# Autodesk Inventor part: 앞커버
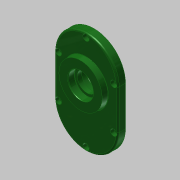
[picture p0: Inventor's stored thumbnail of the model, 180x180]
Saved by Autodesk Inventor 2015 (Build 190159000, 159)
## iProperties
Created: 2016-12
Part Number: 앞커버
Material: 일반
Document SubType Name: Modeling
Designer: mduedu
Density: 1 g/cm^3
Appearance: 매끄러움 - 짙은 산림 녹색
Mass: 97.664 g
Surface Area: 264.413 cm^2
Volume: 97.664 cm^3
Author: mduedu
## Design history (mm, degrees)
sketch "스케치1"
  geometry: L1 (40, -25)-(40, 25); L2 (-40, 25)-(-40, -25); L3 (-40, -25)-(40, 25); L4 (40, -25)-(-40, 25); A1 r 40 centre (0, 25) between (40, 25) and (-40, 25); A2 r 40 centre (0, -25) between (-40, -25) and (40, -25); 1 further point
  constraints: 8 end point, 4 point on circle, 4 tangent, 2 centre point, 2 midpoint, 1 parallel, 1 vertical
  dimensions: "d0" = 130 dimension on A2 A1; "d2" = 80 distance between parallel lines of L1 L2
extrude "돌출1" new body sketch "스케치1" distance "d3" = 10; taper "d4" = 0 deg
sketch "스케치2"
  geometry: C1 r 21 at (0, 11); 1 further point
  constraints: 1 centre point, 1 vertical alignment
  dimensions: "d5" = 42 diameter of C1; "d7" = 11 distance of C1.centre point (0, 0)
extrude "돌출2" join sketch "스케치2" distance "d8" = 7; taper "d9" = 0 deg
sketch "스케치3"
  geometry: C1 r 15 at (0, -33.1); C2 r 21 at (0, 11) reference; 1 further point
  constraints: 1 centre point, 1 vertical alignment
  dimensions: "d10" = 30 diameter of C1; "d71" = 44.1 distance of C1.centre C2.centre
extrude "돌출3" join sketch "스케치3" distance "d12" = 7; taper "d13" = 0 deg
sketch "스케치4"
  geometry: C1 r 28 at (0, 11); A1 r 21 centre (0, 11) between (8.978, -7.984) and (-8.978, -7.984) reference; 1 further point
  constraints: 1 centre point, 1 coincident
  dimensions: "d14" = 56 diameter of C1
extrude "돌출4" join sketch "스케치4" distance "d15" = 7; taper "d16" = -5 deg
hole "구멍1" diameter "d19" = 35; stored, may be unused: countersink angle "d23" = 90 deg, drill point angle "d25" = 0 deg; dims "d17" = 10, "d18" = 10, "d20" = 6, "d21" = 4, "d22" = 2, "d24" = 10
hole "구멍2" diameter "d28" = 22; stored, may be unused: countersink angle "d32" = 90 deg, drill point angle "d34" = 0 deg; dims "d26" = 10, "d27" = 10, "d29" = 6, "d30" = 4, "d31" = 2, "d33" = 7
hole "구멍3" diameter "d37" = 19; stored, may be unused: countersink angle "d41" = 90 deg, drill point angle "d43" = 0 deg; dims "d35" = 10, "d36" = 10, "d38" = 6, "d39" = 4, "d40" = 2, "d42" = 1
hole "구멍4" diameter "d46" = 32; stored, may be unused: countersink angle "d50" = 90 deg, drill point angle "d52" = 0 deg; dims "d47" = 6, "d48" = 4, "d49" = 2, "d51" = 8.3, "d89" = 10, "d90" = 10
hole "구멍5" diameter "d55" = 25; stored, may be unused: countersink angle "d59" = 90 deg, drill point angle "d61" = 0 deg; dims "d53" = 10, "d54" = 10, "d56" = 6, "d57" = 4, "d58" = 2, "d60" = 8
fillet "모깎기1" dims "d62" = 0.3
fillet "모깎기2" dims "d63" = 2
chamfer "모따기1" distance "d64" = 1; stored, may be unused: second distance "d65" = 2, angle "d66" = 45 deg
chamfer "모따기2" distance "d91" = 0.8; stored, may be unused: second distance "d92" = 2, angle "d93" = 30 deg
fillet "모깎기4" dims "d68" = 2
fillet "모깎기5" dims "d69" = 0.3
fillet "모깎기6" dims "d70" = 2
sketch "스케치5"
  geometry: L1 (-40, 25)-(-40, -25) reference; L2 (40, -25)-(40, 25) reference; L3 (35, 25)-(35, -25); L4 (-35, -25)-(-35, 25); A1 r 40 centre (0, 25) between (40, 25) and (-40, 25) reference; A2 r 40 centre (0, -25) between (-40, -25) and (40, -25) reference; A3 r 35 centre (0, 25) between (35, 25) and (-35, 25); A4 r 35 centre (0, -25) between (-35, -25) and (35, -25); 2 further points
  constraints: 5 point on circle, 4 end point, 2 centre point, 1 vertical alignment, 3 other
  dimensions: "d72" = 5 distance between parallel lines of L2 L3
sketch "스케치7"
  geometry: 1 further point
  constraints: 1 other
hole "구멍7" sketch "스케치7" at (0, 60) diameter "d80" = 4.5; stored, may be unused: countersink angle "d84" = 90 deg, drill point angle "d86" = 0 deg; dims "d81" = 6, "d82" = 8, "d83" = 4.6, "d85" = 8
node "솔리드1"
pattern_linear "직사각형 패턴1"
